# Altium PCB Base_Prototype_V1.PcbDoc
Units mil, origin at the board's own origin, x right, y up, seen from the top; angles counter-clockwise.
Board outline 4328.9 x 1639.92 mil, 2 copper layers (Top Layer, Bottom Layer); 71 components, 85 nets, 339 pads, 159 vias.
Unrouted connection lines stored in the file: 97.
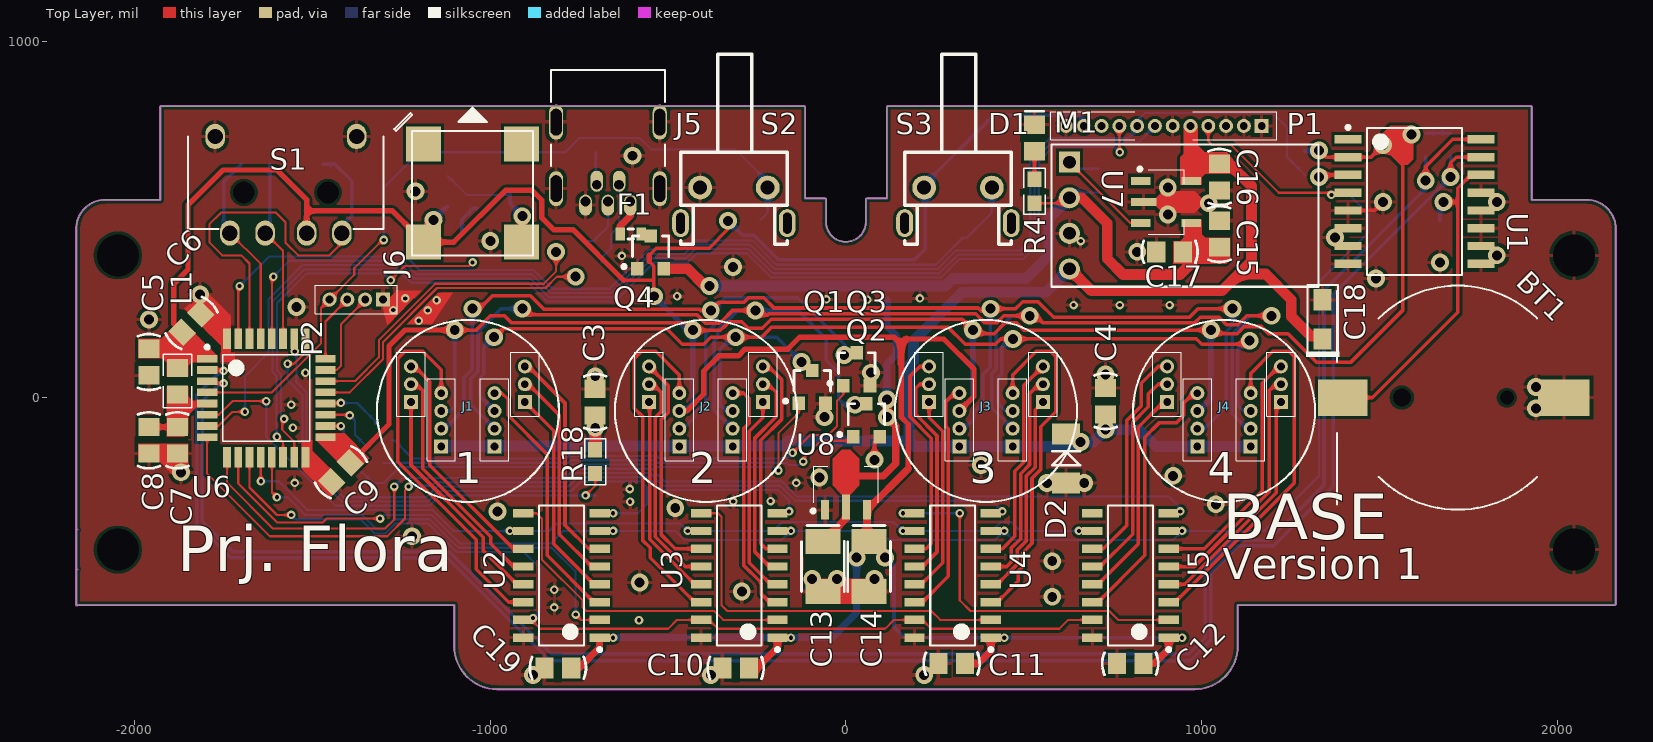
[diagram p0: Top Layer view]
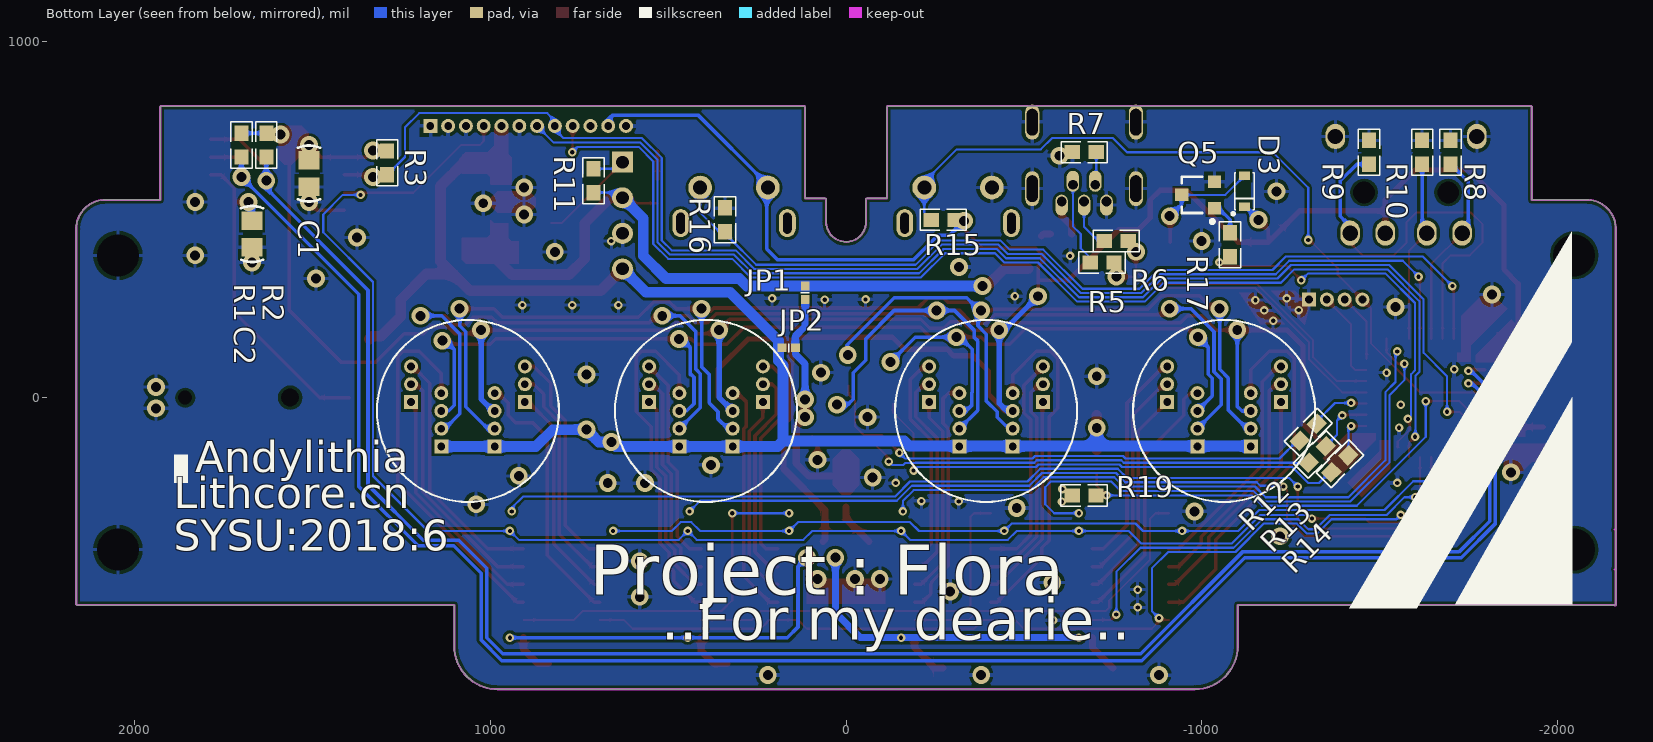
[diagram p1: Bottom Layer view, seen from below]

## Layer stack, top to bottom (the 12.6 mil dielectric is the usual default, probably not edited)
Top Solder: solder mask 0.4, Solder Resist, Dk 3.5
Top Layer: signal copper 1.4
Dielectric 1: dielectric 12.6, FR-4, Dk 4.8
Bottom Layer: signal copper 1.4
Bottom Solder: solder mask 0.4, Solder Resist, Dk 3.5

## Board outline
-2161.42,-583.68 -1101.39,-583.68 -1101.39,-698.82 ccw(c-980.32,-698.82) -981.2,-819.89 ccw(c-980.31,-816.93) -980.31,-820.02 ccw(c-980.31,-816.93) -979.44,-819.9 980.31,-819.9 ccw(c980.31,-698.82) 1101.39,-698.82 1101.39,-583.68 2161.42,-583.68 ccw(c2161.42,-580.71) 2164.39,-580.71 2164.39,473.54 ccw(c2161.42,474.41) 2164.51,474.41 ccw(c2161.42,474.41) 2164.38,475.3 ccw(c2082.68,474.41) 2082.68,556.12 1928.16,556.12 1928.16,816.93 ccw(c1925.2,816.93) 1925.2,819.9 118.11,819.9 ccw(c118.11,816.93) 115.14,816.93 115.14,560.05 59.06,560.05 ccw(c59.06,557.09) 56.09,557.09 56.05,496.06 ccw(c59.02,496.06) 56.06,495.96 cw(c0,494.09) 56.09,494.09 cw(c0,494.09) -56.06,495.96 ccw(c-59.02,496.06) -56.05,496.06 ccw(c-59.02,496.06) -56.05,496.06 -56.09,557.09 cw(c-59.06,557.09) -56.09,557.09 ccw(c-59.06,557.09) -59.06,560.05 -115.14,560.05 -115.14,816.93 ccw(c-118.11,816.93) -118.11,819.9 -1925.2,819.9 ccw(c-1925.2,816.93) -1928.16,816.93 -1928.16,556.12 -2082.68,556.12 ccw(c-2082.68,474.41) -2164.39,474.41 ccw(c-2161.42,474.41) -2164.39,474.39 -2164.39,-580.71 ccw(c-2161.42,-580.71)

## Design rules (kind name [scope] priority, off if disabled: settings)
AssemblyTestPointUsage [All] p1 off:
AssemblyTestpoint [All] p1 off: testpointundercomponent=TRUE minsize=40 maxsize=100 preferedsize=60 minholesize=0 maxholesize=40 preferedholesize=32 testpointgrid=1 usegrid=TRUE gridtolerance=0.01 allowsidetop=TRUE allowsidebottom=TRUE
Clearance [All] p1: gap=6 ignorepadtopadclearanceinfootprint=FALSE except(0: Arc-Hole Track-Hole SMDPad-Hole THPad-Hole Via-Hole Fill-Hole Poly-Hole Region-Hole Text-Hole; 8: Arc-Fill Arc-Poly Arc-Region Track-Fill Track-Poly Track-Region SMDPad-Fill SMDPad-Poly SMDPad-Region THPad-Fill THPad-Poly THPad-Region Via-Fill Via-Poly Via-Region Fill-Fill Fill-Poly Fill-Region Poly-Poly Poly-Region Region-Region)
ComponentClearance [All] p1 off: gap=10 collisioncheckmode=3 verticalgap=10 showdistances=FALSE
FabricationTestPointUsage [All] p1 off: valid=0 allowmultiple=FALSE
FabricationTestpoint [All] p1 off: side=3 testpointundercomponent=TRUE minsize=40 maxsize=100 preferedsize=60 minholesize=0 maxholesize=40 preferedholesize=32 testpointgrid=1 allowsidetop=TRUE allowsidebottom=TRUE usegrid=TRUE gridtolerance=0.01
FanoutControl Fanout_BGA [IsBGA] p1 off: bgadir=Out bgaviamode=Centered fanoutstyle=Auto fanoutdirection=Alternating viagrid=1 // Fanout_BGA (Default Rule)
FanoutControl Fanout_LCC [IsLCC] p2 off: bgadir=Out bgaviamode=Centered fanoutstyle=Auto fanoutdirection=Alternating viagrid=1 // Fanout_LCC (Default Rule)
Height [All] p1 off: minheight=0 maxheight=1000 prefheight=500
MinimumSolderMaskSliver [All] p1 off: minsoldermaskwidth=10
PolygonConnect [All] p1: connectstyle=Relief reliefconductorwidth=10 reliefentries=4 polygonreliefangle="90 Angle" airgapwidth=10
RoomDefinition RTCModule [InComponentClass('RTCModule')] p1: confinementstyle=ConfineIn formatcopy=TRUE lockcomponents=FALSE outline 1245,-330 2105,-330 2105,790 1245,790
RoomDefinition IV9Driv [InComponentClass('IV9Driv')] p2: confinementstyle=ConfineIn formatcopy=TRUE lockcomponents=FALSE outline -1335,-805 1335,-805 1335,270 -1335,270
RoomDefinition TOP [InComponentClass('TOP')] p3: confinementstyle=ConfineIn formatcopy=TRUE lockcomponents=FALSE outline -2005,-595 1480,-595 1480,1050 -2005,1050
RoutingVias [All] p1: holewidth=28 width=50 viastyle="Through Hole" minholewidth=28 minwidth=50 maxholewidth=28 maxwidth=50
SilkToSilkClearance [All] p1 off: silktosilkclearance=10
SilkToSolderMaskClearance [IsPad] p1 off: minsilkscreentomaskgap=10 clearancetoexposedcopper=TRUE
SolderMaskExpansion [All] p1: expansion=4
Width [All] p1: maxlimit=50 minlimit=6 preferedwidth=10 minimp=50.000000 maximp=50.000000 favimp=50.000000
19 further rules are at their usual default settings.

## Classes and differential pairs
component class RTCModule: BT1 C1 C2 R1 R2 R3 U1
component class TOP: C3 C4 C5 C6 C7 C8 C9 C13 C14 C15 C16 C17 C18 D1 D3 F1 J5 J6 JP1 JP2 L1 M1 P1 P2 Q4 Q5 R4 R5 R6 R7 R8 R9 R10 R11 R12 R13 R14 R15 R16 R17 R18 R19 S1 S2 S3 U6 U7 U8
component class IV9Driv: C10 C11 C12 C19 D2 J1 J2 J3 J4 Q1 Q2 Q3 Q? U2 U3 U4 U5

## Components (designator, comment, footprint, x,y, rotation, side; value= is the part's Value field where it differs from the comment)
BT1 "CR1220" CR1220_Holder_SMT 1720.47,0 r180 top
C1 "Cap" C-RAD-0805 1510,630 r90 bottom value=100nF
C2 "Cap" C-RAD-0805 1670,460 r90 bottom value=100nF
C3 "Cap" C-RAD-0805 -705,-12.6 r270 top value=10uF
C4 "Cap" C-RAD-0805 730,-10 r270 top value=10uF
C5 "Cap" C-RAD-0805 -1960,100 r90 top value=1uF
C6 "Cap" C-RAD-0805 -1840,210 r225 top value=100nF
C7 "Cap" C-RAD-0805 -1880,-120 r90 top value=1uF
C8 "Cap" C-RAD-0805 -1960,-120 r90 top value=100nF
C9 "Cap" C-RAD-0805 -1420,-210 r45 top value=100nF
C10 "Cap" C-RAD-0805 -310,-760 r0 top value=100nF
C11 "Cap" C-RAD-0805 297.24,-748.03 r0 top value=100nF
C12 "Cap" C-RAD-0805 799.21,-748.03 r0 top value=100nF
C13 "Cap Pol" CAP-3528 -65,-475 r270 top value=10uF
C14 "Cap Pol" CAP-3528 65,-475 r270 top value=10uF
C15 "Cap" C-RAD-0805 1050,460 r270 top value=100n
C16 "Cap" C-RAD-0805 1050,620 r90 top value=100n
C17 "Cap" C-RAD-0805 910,410 r0 top value=1u
C18 "Cap Pol" CAP-3216 1340,220 r90 top value=10uF
C19 "Cap" C-RAD-0805 -810,-760 r0 top value=100nF
D1 "USB_PPresent" LED_0805 530,730 r90 top
D2 "Diode-Z" DIODE-1206 618.7,-240 r90 top value=5.1V
D3 "Diode" "SOD323 - INV" -1120,580 r90 bottom
F1 "Fuse" J1-0603 -605,460 r0 top value=800mA
J1 "Kartusche" KARTUSCHE_HDR_EConn -1062.99,-37.4 r0 top
J2 "Kartusche" KARTUSCHE_HDR_EConn -393.7,-37.4 r0 top
J3 "Kartusche" KARTUSCHE_HDR_EConn 393.7,-37.4 r0 top
J4 "Kartusche" KARTUSCHE_HDR_EConn 1062.99,-37.4 r0 top
J5 "USB-Mini-TypeB" USB_MINI_TypeB -669.29,551.18 r90 top locked
J6 "Buzzer" 8530S_BUZZER -1050,575 r270 top
JP1 "JMP" R0402 115,295 r270 bottom
JP2 "JMP" R0402 161.3,140 r180 bottom
L1 "Inductor" 0805-1 -1880,46.26 r90 top value=Bead
M1 "MP2315_Module" MP2315_Module 728.35,511.81 r0 top
P1 "Header 12" HDR12X1_1.27mm 893.7,763.78 r180 top
P2 "Header 4" HDR4X1_1.27mm -1301.95,275.76 r180 top
Q1 "MOSFET-N-E" SOT-23 -95,30 r0 top
Q2 "MOSFET-N-E" SOT-23 57.4,-63.74 r0 top
Q3 "MOSFET-N-E" SOT-23 30,80 r0 top
Q4 "MOSFET-P-E" SOT-23 -549.28,408.3 r0 top
Q5 "MOSFET-N-E" SOT-23 -990,570 r90 bottom
R1 "Res1" 0603-1 1700,710 r90 bottom value=10K
R2 "Res1" 0603-1 1630,710 r90 bottom value=10K
R3 "Res1" 0603-1 1290,660 r90 bottom value=10K
R4 "Res1" 0603-1 530,580 r90 top value=10K
R5 "Res1" 0603-1 -720,380 r0 bottom value=100K
R6 "Res1" 0603-1 -760,440 r0 bottom value=100K
R7 "Res1" 0603-1 -670,690 r180 bottom value=100K
R8 "Res1" 0603-1 -1700,690 r90 bottom value=10K
R9 "Res1" 0603-1 -1470,690 r90 bottom value=10K
R10 "Res1" 0603-1 -1620,690 r90 bottom value=10K
R11 "Res1" 0603-1 710,610 r90 bottom value=10K
R12 "Res1" 0603-1 -1300,-97.32 r315 bottom value=20
R13 "Res1" 0603-1 -1325,-160 r315 bottom value=20
R14 "Res1" 0603-1 -1388.66,-186.34 r315 bottom value=20
R15 "Res1" 0603-1 -273.46,500 r0 bottom value=10K
R16 "Res1" 0603-1 340,500 r90 bottom value=10K
R17 "Res1" 0603-1 -1080,430 r90 bottom value=20
R18 "Res1" 0603-1 -705,-180 r270 top value=10K
R19 "Res1" 0603-1 -669.29,-275 r0 bottom value=10K
S1 "Quad Encoder" SIQ-02FVS1_03_r -1574.8,753.94 r0 top locked
S2 "SW-PB" SW_PB2_C1 -314.96,590.55 r0 top locked
S3 "SW-PB" SW_PB2_C1 314.96,590.55 r0 top locked
U1 "DS3231" "16 SO (Maxim W16#H2)" 1598.43,551.18 r0 top
U2 "TLC6C598" SOIC16N -800,-500 r180 top
U3 "TLC6C598" SOIC16N -300,-500 r180 top
U4 "TLC6C598" SOIC16N 300,-500 r180 top
U5 "TLC6C598" SOIC16N 800,-500 r180 top
U6 "STM32 MCU" TQFP80P900X900X160-32N -1297.24,-333.66 r0 top
U7 "XC6503CZxx-G" SOT-89-5 900,550 r0 top
U8 "HT73XX LDO" SOT89-150P409X160-3N 0,-245 r90 top

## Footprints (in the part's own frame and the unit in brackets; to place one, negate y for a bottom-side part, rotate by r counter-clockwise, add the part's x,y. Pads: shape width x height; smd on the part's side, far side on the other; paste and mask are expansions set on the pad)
"16 SO (Maxim W16#H2)" [mm] "SOP, 16-Leads, Body 10.30x7.50mm, Pitch 1.27mm, IPC Medium Density"
  rect 1.9x0.6 smd: 1(-4.75,4.445) 2(-4.75,3.175) 3(-4.75,1.905) 4(-4.75,0.635) 5(-4.75,-0.635) 6(-4.75,-1.905) 7(-4.75,-3.175) 8(-4.75,-4.445) 9(4.75,-4.445) 10(4.75,-3.175) 11(4.75,-1.905) 12(4.75,-0.635) 13(4.75,0.635) 14(4.75,1.905) 15(4.75,3.175) 16(4.75,4.445)
  silkscreen extent -4.87,-5.25 3.4,5.42, body extent -5.16,-5.25 5.16,5.25, height 2.65
0603-1 [mm] "贴片带丝印"
  rect 1.1x1 smd: 1(-0.85,0) 2(0.85,0)
  silkscreen extent -1.65,-0.76 1.65,0.76, body extent -1.14,-0.38 1.14,0.38, height 1
0805-1 [mm] "贴片带丝印"
  rect 1.3x1.5 smd: 1(-0.95,0) 2(0.95,0)
  silkscreen extent -1.91,-1.02 1.91,1.02, body extent -1.14,-0.51 1.14,0.51, height 1
8530S_BUZZER [mm] "8530S SMT MAGNETIC BUZZER TRANSDUCER"
  rect 2.5x2.5 smd: 1(-3.5,-3.5) 2(3.5,-3.5) 3(3.5,3.5) 4(-3.5,3.5)
  silkscreen extent -6.1,-5.59 4.44,4.32, body extent -4.45,-4.35 4.45,4.35, height 3
C-RAD-0805 [mm] "贴片电容"
  rect 1.3x1.5 smd: 1(-0.95,0) 2(0.95,0)
  silkscreen extent -2,-0.79 2,0.79, body extent -1.27,-0.64 1.27,0.64, height 0.9
CAP-3216 [mil] "钽电容"
  rect 60x50 smd: 1(-55,0) 2(55,0)
  silkscreen extent -106,-48 96,46
CAP-3528 [mm] "钽电容"
  rect 1.8x2.5 smd: 1(-1.778,0) 2(1.778,0)
  silkscreen extent -2.92,-1.52 1.78,1.52, body extent -1.91,-1.4 1.91,1.4, height 1.1
CR1220_Holder_SMT [mm]
  round 0 hole 1 unplated: 0(-3.5,0)
  rect 3.54x2.6 smd: 1(8.23,0)
  rect 3.66x2.6 smd: 2(-7.57,0)
  round 0 hole 1.3 unplated: 9(4,0)
  silkscreen extent -5.66,-8 8.64,8, body extent -9.27,-7.5 9.27,7.5, height 4
DIODE-1206 [mm] "玻璃封装二极管"
  rect 1.5x2 smd: 1(0,0) 2(3.5,0)
  silkscreen extent 1.25,-1 2.25,1
HDR4X1_1.27mm [mm]
  rect 1x1 hole 0.55: 1(0,0)
  round 1 hole 0.55: 2(1.27,0) 3(2.54,0) 4(3.81,0)
  silkscreen extent -1.02,-1.02 4.83,1.02
HDR12X1_1.27mm [mm]
  rect 1x1 hole 0.55: 1(-6.985,0)
  round 1 hole 0.55: 2(-5.715,0) 3(-4.445,0) 4(-3.175,0) 5(-1.905,0) 6(-0.635,0) 7(0.635,0) 8(1.905,0) 9(3.175,0) 10(4.445,0) 11(5.715,0) 12(6.985,0)
  silkscreen extent -8.08,-1 8.08,1
J1-0603 [mm] "Chip Resistor, Body 1.6x0.8mm, IPC High Density"
  rect 0.7x0.9 smd: 1(-0.75,0) 2(0.75,0)
  silkscreen extent -0.2,-0.35 0.2,0.35, body extent -0.85,-0.48 0.85,0.48, height 0.9
KARTUSCHE_HDR_EConn [mm] "IV9 Module"
  rect 1x1 hole 0.55: 1(1.905,-2.54) 5(4.064,0.635) 10(-4.064,0.635) 14(-1.905,-2.54)
  round 1 hole 0.55: 2(1.905,-1.27) 3(1.905,0) 4(1.905,1.27) 6(4.064,1.905) 7(4.064,3.175) 8(-4.064,3.175) 9(-4.064,1.905) 11(-1.905,1.27) 12(-1.905,0) 13(-1.905,-1.27)
  silkscreen extent -6.5,-6.5 6.5,6.5, body extent -5.11,-3.37 5.11,4.01, height 4.3
LED_0805 [mm] "贴片二极管"
  rect 1.3x1.5 smd: 1(-0.95,0) 2(0.95,0)
  silkscreen extent 1.91,-0.63 1.91,0.64
MP2315_Module [mm]
  rect 1.5x1.5 hole 0.9: 1(-2.54,3.81)
  round 1.5 hole 0.9: 2(-2.54,1.27) 3(-2.54,-1.27) 4(-2.54,-3.81)
  silkscreen extent -3.81,-5.08 15.24,5.08
R0402 [mm] "Chip Resistor, 2-Leads, Body 1,0x0,5mm, IPC High Density"
  rect 0.65x0.6 smd mask+0: 1(-0.475,0) 2(0.475,0)
  silkscreen extent 0,-0.3 0,0.3, body extent -0.5,-0.25 0.5,0.25, height 0.38
SIQ-02FVS1_03_r [mm] "Mitsumi Quadrature Encoder Thru Hole Mount"
  round 0 hole 1.55 unplated: 0(-3,-4.5) 0(3,-4.5)
  oval 1.4x1.8 hole 1.1: 1(-4,-7.4) 2(-1.48,-7.4) 3(1.48,-7.4) 4(4,-7.4) 5(-5.05,-0.5) 5(5.05,-0.5)
  silkscreen extent -6.98,-7.11 6.98,-0.51, body extent -7,-7.12 7,7.13, height 5
"SOD323 - INV" [mm] "Molded SOD323, Body 2,7X1,35(MAX)"
  rect 0.6x0.8 smd mask+0: 1(1.1,0) 2(-1.1,0)
  silkscreen extent -1.7,-0.7 1.33,0.9, body extent -1.4,-0.67 1.4,0.68, height 1.1
SOIC16N [mm] "SOIC, 16-Leads, Body 9.90x3.90mm, Pitch 1.27mm, IPC Medium Density"
  rect 1.45x0.6 smd: 1(-2.725,4.445) 2(-2.725,3.175) 3(-2.725,1.905) 4(-2.725,0.635) 5(-2.725,-0.635) 6(-2.725,-1.905) 7(-2.725,-3.175) 8(-2.725,-4.445) 9(2.725,-4.445) 10(2.725,-3.175) 11(2.725,-1.905) 12(2.725,-0.635) 13(2.725,0.635) 14(2.725,1.905) 15(2.725,3.175) 16(2.725,4.445)
  silkscreen extent -2.85,-5 1.6,5.42, body extent -3,-5 3,5, height 1.75
SOT89-150P409X160-3N [mm] "SOT89, 3-Leads, Body 4.50x2.44mm, Pitch 1.50mm, Lead Span 4.1mm, IPC Medium Density"
  rect 1.4x0.6 smd: 1(-1.8,1.499) 3(-1.8,-1.499)
  rect 1.8x0.6 smd: 2(-1.6,0)
  Top Layer region: -0.7,0.3 -0.05,0.95 1.85,0.95 2.5,0.3 2.5,-0.3 1.85,-0.95 -0.05,-0.95 -0.7,-0.3
  silkscreen extent -2,-2.3 1.32,2.47, body extent -2.19,-2.3 1.8,2.3, height 1.6
SOT-23 [mm]
  rect 0.9x0.95 smd: 1(-0.95,-1.175) 2(0.95,-1.175) 3(0,1.175)
  silkscreen extent -2.03,-1.14 1.3,1.18
SOT-89-5 [mm]
  rect 1.4x0.6 smd: 1(-1.8,1.499) 3(-1.8,-1.499) 4(1.8,-1.499) 5(1.8,1.499)
  rect 1.8x0.6 smd: 2(-1.6,0)
  Top Layer region: -0.7,0.3 -0.238,0.762 2.038,0.762 2.5,0.3 2.5,-0.3 2.038,-0.762 -0.238,-0.762 -0.7,-0.3
  silkscreen extent -2,-2.3 1.32,2.47, body extent -1.27,-2.29 1.27,2.29, height 1.5
SW_PB2_C1 [mm] "侧卧微动开关"
  round 1.7 hole 1: 1(-2.413,0) 2(2.413,0)
  oval 1.2x2 hole 0.6 slot 1.5 at 90 deg: 3(-3.81,-2.54) 4(3.81,-2.54)
  silkscreen extent -3.81,-4.06 3.81,9.53
TQFP80P900X900X160-32N [mm] "TQFP, 32-Leads, Body 7.00x7.00mm, Pitch 0.80mm, IPC Medium Density"
  rect 1.45x0.55 smd: 1(-12.675,11.25) 2(-12.675,10.45) 3(-12.675,9.65) 4(-12.675,8.85) 5(-12.675,8.05) 6(-12.675,7.25) 7(-12.675,6.45) 8(-12.675,5.65) 17(-4.225,5.65) 18(-4.225,6.45) 19(-4.225,7.25) 20(-4.225,8.05) 21(-4.225,8.85) 22(-4.225,9.65) 23(-4.225,10.45) 24(-4.225,11.25)
  rect 0.55x1.45 smd: 9(-11.25,4.225) 10(-10.45,4.225) 11(-9.65,4.225) 12(-8.85,4.225) 13(-8.05,4.225) 14(-7.25,4.225) 15(-6.45,4.225) 16(-5.65,4.225) 25(-5.65,12.675) 26(-6.45,12.675) 27(-7.25,12.675) 28(-8.05,12.675) 29(-8.85,12.675) 30(-9.65,12.675) 31(-10.45,12.675) 32(-11.25,12.675)
  silkscreen extent -12.8,5.35 -5.35,12.2, body extent -12.95,3.95 -3.95,12.95, height 1.6
USB_MINI_TypeB [mm]
  oval 1.5x0.9 hole 0.7 copper offset -0.25,0: 1(0,-1.6) 3(0,0) 5(0,1.6)
  oval 1.5x0.9 hole 0.7 copper offset 0.25,0: 2(1.2,-0.8) 4(1.2,0.8)
  rrect100% 2.5x1 hole 0.8 slot 1.9 at 0 deg: 6(0.92,3.7) 6(0.92,-3.7) 6(5.67,-3.7) 6(5.67,3.7)
  silkscreen extent 2.54,-4.06 9.4,4.06, body extent -0.35,-3.85 9.5,3.85, height 5.8

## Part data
BT1: library part Battery_1, "备份电池"
C1 C2 C3 C4 C5 C6 C7 C8 C9 C10 C11 C12 C15 C16 C17 C19: "无极性电容"
C13 C14 C18: "极性电解电容"
D1: library part LED0, "发光二极管"
D2: "稳压二极管"
D3: "二极管", PackageDocument=Sep-1996
F1: library part "Fuse 2", "保险丝"
J1 J2 J3 J4: library part Kartusche_EConn, "IV9 Module"
J5: library part USB-Mini_TypeB
J6: library part Buzzer_8530S_SMT, "Surface Mount Buzzer"
JP1 JP2: "Generic Jumper"
L1: "电感"
M1: "MP2315 3A Step-down Module"
P1 P2: "接插件"
Q1 Q2 Q3 Q5: "N-Channel Enhanced MOSFET", PackageDocument=1995/1996
Q4: "P-Channel Enhanced MOSFET", PackageDocument=1995/1996
R1 R2 R3 R4 R5 R6 R7 R8 R9 R10 R11 R12 R13 R14 R15 R16 R17 R18 R19: "贴片电阻"
S1: library part SIQ_02FVS1, "Slide and Rotary Encoder Switches"
S2 S3: "微动开关"
U1: "Extremely Accurate I2C-Integrated RTC/TCXO/Crystal"
U2 U3 U4 U5: library part TLC6C598-Q1, "Power Logic 8-Bit Shift Register LED Driver"
U6: library part STM32F042K6T6, "ARM?-based 32-bit MCU, up to 32 KB Flash, crystal-less USB FS 2.0, CAN, 9 timers, ADC and comm. interfaces, 2.0 - 3.6 V"
U7: library part XC6503, "TOREX CL Capacitor-Less 500mA Low Power Consumption High Speed LDO Regulator"
U8: library part HT73xx, "HOLTEK Low Power Consumption LDO"

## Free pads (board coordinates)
  round 0 hole 118.11 unplated: 2(-2047.24,-427.17) 2(-2047.24,399.61) 2(2047.24,-427.17) 2(2047.24,399.61) 2(2047.24,399.61)

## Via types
v1: diameter 50, hole 28, Top Layer to Bottom Layer, 84 vias
v2: diameter 24, hole 11.81, Top Layer to Bottom Layer, 75 vias

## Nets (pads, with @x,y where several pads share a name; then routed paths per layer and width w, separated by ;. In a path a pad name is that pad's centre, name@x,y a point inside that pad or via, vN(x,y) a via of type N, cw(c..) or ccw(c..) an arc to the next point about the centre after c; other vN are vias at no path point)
3V3: C1.2 C5.2 C6.2 C9.2 C10.2 C11.2 C12.2 C14.1 C19.2 D3.2 J1.12 J2.12 J3.12 J4.12 J6.2 L1.2 P1.11 R1.2 R2.2 R3.2 R15.1 S1.3 S3.1 U1.2 U2.1 U3.1 U4.1 U5.1 U6.1 U6.17 U8.3 | length 13879.4
  Top Layer w10: C6.2 -1796.26,113.37 U6.1 ; U6.17 -1463.58,-113.52 C9.2@-1403.55,-173.55 ; J6.2 -1187.8,472.2 v1(-1160,500) ; v1(-1100,190) -1040,190 -1000,230 -960,230 -940,210 -450.71,210 v1(-430.71,190) -429.71,189 -353.34,189 -343.84,198.5 -343.12,198.5 -328.62,213 -293,213 -275,195 -235,195 -210,220 326.69,220 v1(356.69,190) 366.69,180 416.69,180 446.69,210 480,210 500,190 v1(1025.98,190) 1035.98,180 1100,180 1120,200 1167.36,200 1187.36,180 1242.63,180 1322.63,100 1420,100 1565,245 1565,655 v1(1510,710) 1476.18,676.18 U1.2 1348.68,676.18 v1(1330,694.86) ; -625,330 -540.6,330 ; -553.32,383.32 -540.6,370.6 -540.6,330 ; -553.32,400.53 -533.53,420.32 -384.82,420.32 -332,473.14 v1(-332,497) ; v1(-540,285) -540.6,285.6 -540.6,330
  Top Layer w15: C5.2 C5.2@-1933.74,137.4 ; L1.2 C5.2@-1933.74,137.4 ; S1.3 -1516.54,525 ; C9.2 -1285,-75 -1285,145 -1240,190 v1(-1100,190) ; -625,330 -767.2,472.2 -822.2,472.2 -855,505 -855,555 -882.6,582.6 -957.4,582.6 -1102.8,437.2 J6.2 -1275.59,525 -1516.54,525 ; -553.32,383.32 -553.32,400.53 ; J2.12 -447.4,-37.4 -400,10 -400,75 -357.5,117.5 -302.5,117.5 -283.75,136.25 -163.75,136.25 -130,170 135,170 155,150 ; 155,95 155,-55 175,-75 175,-199.87 ; 170,165 275,165 360,80 360,3.9 J3.12 ; C5.2@-1933.74,137.4 -1912.6,137.4 C6.2 -1890,207.11 -1890,320 -1850,360 -1850,541.81 -1751.81,640 -1600,640 -1516.54,556.54 -1516.54,525
  Top Layer w20: C19.2@-750,-760 -692.72,-702.72 U2.1 ; C10.2 -250,-760 -192.72,-702.72 U3.1 ; C14.1 59,-399 U8.3 175,-199.87 ; 155,95 155,150 170,165 ; C11.2 371.97,-748.03 407.28,-712.72 U4.1 ; C12.2 866.97,-748.03 907.28,-707.72 U5.1
  Bottom Layer w10: v1(-1160,500) -1123.31,536.69 D3.2 ; J1.12 -1112.4,-37.4 -1100,-25 v1(-1100,190) ; v1(-332,497) -292,457 -259.17,457 -189.87,387.7 192.7,387.7 223.07,418.07 223.07,601.54 416,794.46 655.54,794.46 668.7,781.3 P1.11 ; v1(110,-450) 135,-475 135,-645 165,-675 v2(445,-675) v2(945,-675) ; R3.2 1328.6,693.46 v1(1330,694.86) ; R2.2 R1.2
  Bottom Layer w15: v1(-540,285) -445,190 v1(-430.71,190) -430.71,-15.71 -452.4,-37.4 J2.12 ; J3.12 356.69,0.59 v1(356.69,190) ; J4.12 992.6,-37.4 1025.98,-4.02 v1(1025.98,190)
  Bottom Layer w20: v2(-655,-675) v2(-155,-675) -40,-675 30,-605 v1(30,-450)
  other v1: 1590,740
ADC_IN0: R18.2 R19.1 U6.6 | length 1374.5
  Top Layer w6: U6.6 -1763.23,-48.23 -1725,-10 v2(-1630,-10) ; v2(-732.28,-275) -705,-247.72 R18.2
  Bottom Layer w6: v2(-1630,-10) -1630,-110 -1436,-304 -1170.06,-304 -1141.06,-275 v2(-732.28,-275) R19.1
AUX_KEY: R16.1 S3.2 U6.31 | length 2552.6
  Top Layer w6: U6.31 -1708.66,310.04 v2(-1705,313.7)
  Bottom Layer w6: v2(-1705,313.7) -1622.02,396.68 -1236.68,396.68 -1199,359 -878.09,359 -825.09,306 -664.91,306 -554.91,416 -459.91,416 -433.91,442 -263.97,442 -195.67,373.7 252.79,373.7 329.09,450 340,450 409.96,519.96 S3.2
GND: BT1.2 C1.1 C2.1 C3.1 C4.1 C5.1 C6.1 C7.1 C8.1 C9.1 C10.1 C11.1 C12.1 C13.2 C14.2 C15.1 C16.1 C17.1 C18.2 C19.1 D1.2 D2.1 J5.5 J5.6 M1.3 P1.1 P1.2 P1.3 P1.6 P1.12 P2.1 pad.2@2047.24,399.61 pad.2@2047.24,-427.17 Q1.2 Q2.2 Q3.2 Q4.1 Q5.2 R7.1 R8.2 R9.2 R10.2 R16.2 R19.2 S1.5 S2.1 U1.5 U1.6 U1.7 U1.8 U1.9 U1.10 U1.11 U1.12 U1.13 U2.16 U3.16 U4.16 U5.16 U6.16 U6.32 U7.2 U8.1 | length 370.2
  Top Layer w10: C6.1 -1811.25,236.45 U6.32 ; U6.16 -1515.57,-167.32 C9.1@-1456.45,-226.45 ; v1(80,-175) 80,-124.8 Q2.2 ; U1.5 1486.18,526.18 v1(1510,550)
  other v1: -880,-780 -380,-780 220,-780 580,-560 -293,-545 -580,-520 -95,-510 -25,-510 80,-510 580,-460 -1220,-390 -980,-320 -480,-310 1040,-300 565,-240 670,-240 -75,-225 920,-220 -1870,-210 380,-190 -60,-55 1940,-30 1940,30 -705,60 730,65 70,70 -1960,220 -1545,255 -1816.34,289.56 1490,335 -318,367 1670,380 1830,400 818.7,410 -1000,440 1375,450 905,515 1020,546.54 1830,550 -1210,580 905,590.55 -600,680
  other v2: -582,-626 -820,-590 -820,-540 -607,-293 -317,-292 -212,-291 -608,-257 -1550,-240 -140,-240 -1555,-85 -1560,-20 -1520,70 -1710,80 -1201,216 -1176,245 -1273,246 640,260 770,260 910,260 -1151,274 60,275 -55,276 -1239,279 208,279 -475,285 -630,398.56 660,440
GPIO_EXTI5: P1.8 R3.1 U1.3 U6.28 | length 3753.9
  Top Layer w6: U6.28 -1614.17,335.83 v2(-1610,340)
  Top Layer w10: v1(1330,620) 1336.18,626.18 U1.3
  Bottom Layer w6: v2(-1610,340) -1565.32,384.68 -1246.02,384.68 -1208.34,347 -883.06,347 -830.06,294 -659.94,294 -549.94,404 -454.94,404 -428.94,430 -268.94,430 -200.64,361.7 257.76,361.7 310.06,414 490.06,414 518,441.94 518,674 574,730 795,730 818.7,753.7 P1.8 818.7,778.7 840,800 1200,800 1240,760 1240,676.54 R3.1
I2C1_SCL: R2.1 U1.16 U6.3 | length 5353.7
  Top Layer w10: U6.3 -1790,40 v2(-1750,40) ; v1(1630,610) 1630,650 1706.18,726.18 U1.16
  Bottom Layer w10: v2(-1750,40) -1760,40 -1810,-10 -1810,-347.37 -1723.37,-434 -1114.74,-434 -828.74,-720 965,-720 1010,-675 1010,-479.8 1088.8,-401 1188.6,-401 1344,-245.6 1344,302.23 1630,588.23 v1(1630,610) R2.1
I2C1_SDA: R1.1 U1.15 U6.2 | length 5377.2
  Top Layer w10: U6.2 -1752.24,77.76 -1750,75.51 v2(-1750,75) ; v1(1700,620) 1700,660 1716.18,676.18 U1.15
  Bottom Layer w10: v2(-1750,75) -1757.53,75 -1826,6.53 -1826,-354 -1730,-450 -1121.37,-450 -831.37,-740 967.63,-740 1026,-681.63 1026,-494 1103,-417 1203,-417 1370,-250 1370,290.91 1699.09,620 v1(1700,620) R1.1
IV9_LATCH: U2.10 U3.10 U4.10 U5.10 U6.12 | length 2479.8
  Top Layer w6: U6.12 -1645.67,-229.33 v2@-1645,-230
  Bottom Layer w6: v2(-1645,-235) -1595,-235 -1514,-316 -1162.03,-316 -1103.03,-375 v2(-945,-375) -835,-375 -814,-354 -466,-354 v2(-445,-375) -205,-375 -180,-350 135,-350 v2(160,-375) 410,-375 435,-350 465,-350 490,-375 v2(655,-375)
NetBT1_1: BT1.1 C2.2 U1.14 | length 949.6
  Top Layer w10: BT1.1 1480,0 1720,240 1720,550 ; v1(1680,550) 1720,550 ; U1.14 1757.09,626.18 1720,589.09 1720,550
  Bottom Layer w10: C2.2 1670,540 v1(1680,550)
NetC7_2: C7.2 C8.2 L1.1 U6.5 | length 265.8
  Top Layer w15: C8.2 C7.2 L1.1 -1875.59,8.86 -1850,-16.73 U6.5
NetC13_1: C13.1 JP1.2 JP2.2 U8.2 | length 767.9
  Top Layer w20: C13.1 0,-340 U8.2 ; 5,-220 105,-220 140,-185 140,-80 v1(115,-55) v1(115,-5)
  Bottom Layer w20: v1(115,-5) 115,95 142.6,122.6 JP2.2 142.6,172.4 115,200 JP1.2
NetD1_1: D1.1 R4.2 | length 79.1
  Top Layer w10: R4.2 D1.1
NetD3_1: D3.1 J6.3 Q5.3 | length 346
  Top Layer w10: J6.3 -912.2,507.8 v1(-910,510)
  Bottom Layer w6: D3.1 -1066.69,570 Q5.3
  Bottom Layer w10: Q5.3 -943.74,543.74 v1(-910,510)
NetF1_1: F1.1 J5.1 | length 102.9
  Top Layer w20: F1.1 -634.53,482.96 -606.3,511.19 J5.1
NetF1_2: F1.2 Q4.3 | length 28.4
  Top Layer w20: F1.2 -554.72,460 Q4.3
NetJ1_2: J1.2 J2.2 J3.2 J4.2 Q2.3 | length 4437.5
  Top Layer w10: v1(-910,250) -910,246 -923,233 -418.91,233 -394.91,209 -355.96,209 -350.46,214.5 -349.75,214.5 -319.25,245 v1(-255,245) -242,232 -220.63,232 -216.63,236 365,236 391,210 424.07,210 444.07,230 v1(516.69,230) 535,230 555,210 980,210 996,226 1049.07,226 1070.07,205 1101.69,205 1126.69,230 v1(1196.69,230)
  Bottom Layer w10: J1.2 -1055,-20.39 -1055,52.37 -1034.68,72.7 -1034.68,185.32 -970,250 v1(-910,250) ; J2.2 -370,-36.1 -370,7.37 -371,8.37 -371,159 -360,170 -360,190 -305,245 v1(-255,245) -135,245 -55,165 -55,105 -20,70 -20,-5 5,-30 15,-20 v1(25,-20) ; J3.2 410,-28.7 410,67.37 422.02,79.39 422.02,185.32 466.69,230 v1(516.69,230) ; J4.2 1127.4,-87.4 1085.69,-45.69 1085.69,179 1136.69,230 v1(1196.69,230)
NetJ1_3: J1.3 J2.3 J3.3 J4.3 Q1.3 | length 3429.6
  Top Layer w10: v1(-990,170) -988.28,168.28 -962.56,194 -504,194 -460,150 -400,150 -380,170 v1(-310,170) -237.37,170 -209.37,198 287,198 335,150 420,150 435,165 v1(470,165) 474.94,165 475,165.06 984.94,165.06 1000,150 1115,150 1125,160 v1(1135,160)
  Bottom Layer w10: v1(-990,170) -1018.68,141.32 -1018.68,66.07 -1030,54.75 -1030,4.61 J1.3 ; J2.3 -337.6,-37.4 -354,-21 -354,14 -355,15 -355,135.71 -320.71,170 v1(-310,170) -195,170 v1(-125,100) ; J3.3 447.4,-37.4 427.5,-17.5 427.5,57.5 435,65 438.02,65 438.02,141.32 461.69,165 v1(470,165) ; v1@1135.98,170 1101.69,135.71 1101.69,-21.69 1117.4,-37.4 J4.3
NetJ1_4: J1.4 U2.3 | length 731.1
  Top Layer w10: J1.4 -967.6,12.6 -950,-5 -950,-50 -840,-160 -840,-443.43 -708.43,-575 U2.3
NetJ1_5: J1.5 U2.4 | length 608.9
  Top Layer w10: J1.5 -822,-93.39 -822,-411.43 -708.43,-525 U2.4
NetJ1_6: J1.6 U2.5 | length 618.8
  Top Layer w10: J1.6 -892.6,37.6 -806,-49 -806,-384 -715,-475 U2.5
NetJ1_7: J1.7 U2.6 | length 623.8
  Top Layer w10: J1.7 -892.6,87.6 -790,-15 -790,-358.43 -723.43,-425 U2.6
NetJ1_8: J1.8 U2.11 | length 665.7
  Top Layer w10: J1.8 -1212.6,87.6 -1170,45 -1170,-190 -935,-425 U2.11
NetJ1_9: J1.9 U2.12 | length 668.6
  Top Layer w10: J1.9 -1207.6,37.6 -1190,20 -1190,-200 -998.75,-391.25 -998.75,-411.25 -935,-475 U2.12
NetJ1_10: J1.10 U2.13 | length 653.7
  Top Layer w10: J1.10 -1222.99,-189.64 -1020,-392.63 -1020,-430 -925,-525 U2.13
NetJ1_11: J1.11 U2.14 | length 1072.1
  Top Layer w10: J1.11 -1137.99,77.99 -1190,130 -1240,130 -1260,110 -1260,-180 -1040,-400 -1040,-482.88 -947.88,-575 U2.14
NetJ1_13: J1.13 J2.13 J3.13 J4.13 Q3.3 | length 4278.1
  Top Layer w10: v1(-1050,250) -1030,250 -994,286 -887.26,286 -850.26,249 -412.28,249 -408.28,245 v1(-380,245) -357.5,267.5 -287.58,267.5 -274.08,281 -231.49,281 -202.49,252 371.63,252 380.63,243 399.69,243 v1(406.69,250) 476.69,250 496.69,270 540,270 584,226 966,226 990,250 v1(1086.69,250)
  Bottom Layer w10: J1.13 -1127.4,-87.4 -1075,-35 -1075,55 -1050.68,79.32 -1050.68,249.32 v1(-1050,250) ; J2.13 -468.7,-79 -449,-79 -425,-55 -425,-40 -394.71,-9.71 -394.71,177.92 -371,201.63 -371,241 v1@-375,245 ; v1(-5,120) -5,145 -2.5,147.5 -136,281 -339,281 v1@-375,245 ; J3.13 332.6,-87.4 360,-60 360,-40 385,-15 385,65 406.02,86.02 406.02,249.32 v1(406.69,250) ; J4.13 1007.6,-87.4 1069.69,-25.31 1069.69,185.63 1085.69,201.63 1085.69,241 1076.69,250 v1(1086.69,250) ; v1@-375,245 -380,250 v1(-380,245) v1@-375,245
NetJ2_4: J2.4 U3.3 | length 683.8
  Top Layer w10: J2.4 -287.6,12.6 -272.6,-2.4 -272.6,-72.57 -288,-87.97 -288,-471.05 -241.21,-517.84 -241.21,-520.74 -239.32,-522.63 -239.32,-522.84 -238,-524.16 -238,-552 -215,-575 U3.3
NetJ2_5: J2.5 U3.4 | length 572.3
  Top Layer w10: J2.5 -233.7,-56.3 -272,-94.6 -272,-464.43 -211.43,-525 U3.4
NetJ2_6: J2.6 U3.5 | length 601.2
  Top Layer w10: J2.6 -218.6,37.6 -196,15 -196,-53.37 -256,-113.37 -256,-434 -215,-475 U3.5
NetJ2_7: J2.7 U3.6 | length 607.6
  Top Layer w10: J2.7 -217.6,87.6 -180,50 -180,-60 -240,-120 -240,-410 -225,-425 U3.6
NetJ2_8: J2.8 U3.11 | length 632.3
  Top Layer w10: J2.8 -500,33.9 -500,-42.63 -520,-62.63 -520,-384.75 -479.75,-425 U3.11
NetJ2_9: J2.9 U3.12 | length 617.8
  Top Layer w10: J2.9@-537.7,31.63 -543.67,37.6 -542.6,37.6 -520,15 -520,-40 -536,-56 -536,-391.37 -452.37,-475 U3.12
NetJ2_10: J2.10 U3.13 | length 583.6
  Top Layer w10: J2.10 -552,-14.1 -552,-398 -425,-525 U3.13
NetJ2_11: J2.11 U3.14 | length 980.4
  Top Layer w10: J2.11@-468.7,18.5 -468.7,63.7 -535,130 -575,130 -595,110 -595,-30 -571.9,-53.1 -571.9,-400.73 -550,-422.63 -550,-450 -425,-575 U3.14
NetJ3_4: J3.4 U4.3 | length 982.1
  Top Layer w10: U4.3 425,-575 485,-515 485,-487.63 496.96,-475.67 496.96,-435.92 523,-409.88 523,-227 548,-202 548,-82 590,-40 590,115 575,130 535,130 468.7,63.7 J3.4
NetJ3_5: J3.5 U4.4 | length 583.6
  Top Layer w10: U4.4 425,-525 480.96,-469.04 480.96,-429.29 507,-403.25 507,-220.37 532,-195.37 532,-34.1 J3.5
NetJ3_6: J3.6 U4.5 | length 606.2
  Top Layer w10: U4.5 452.37,-475 464.96,-462.41 464.96,-422.67 491,-396.63 491,-213.75 516,-188.75 516,11 542.6,37.6 J3.6
NetJ3_7: J3.7 U4.6 | length 592.4
  Top Layer w10: U4.6 440,-425 475,-390 475,-207.12 500,-182.12 500,33.9 J3.7
NetJ3_8: J3.8 U4.11 | length 613.5
  Top Layer w10: U4.11 225,-425 240,-410 240,-113.84 180,-53.84 180,60 207.6,87.6 J3.8
NetJ3_9: J3.9 U4.12 | length 607.6
  Top Layer w10: U4.12 215,-475 256,-434 256,-107.21 196,-47.21 196,26 207.6,37.6 J3.9
NetJ3_10: J3.10 U4.13 | length 571
  Top Layer w10: U4.13 211.43,-525 272,-464.43 272,-94.6 233.7,-56.3 J3.10@233.7,-13.7
NetJ3_11: J3.11 U4.14 | length 655.6
  Top Layer w10: U4.14 215,-575 288,-502 288,-87.97 280,-79.97 280,-12.54 J3.11@306.37,13.83
NetJ4_4: J4.4 U5.3 | length 1055.8
  Top Layer w10: U5.3 925,-575 1260,-240 1260,115 1245,130 1200,130 1137.99,67.99 J4.4
NetJ4_5: J4.5 U5.4 | length 669.8
  Top Layer w10: U5.4 952.37,-525 1210,-267.37 1210,-25.39 J4.5
NetJ4_6: J4.6 U5.5 | length 694.8
  Top Layer w10: U5.5 979.75,-475 1190,-264.75 1190,20 1207.6,37.6 J4.6
NetJ4_7: J4.7 U5.6 | length 705
  Top Layer w10: U5.6 1007.12,-425 1170,-262.12 1170,40 1217.6,87.6 J4.7
NetJ4_8: J4.8 U5.11 | length 632.6
  Top Layer w10: U5.11 723.43,-425 790,-358.43 790,-63.37 830,-23.37 830,40 877.6,87.6 J4.8
NetJ4_9: J4.9 U5.12 | length 627.6
  Top Layer w10: U5.12 715,-475 806,-384 806,-70 850,-26 850,10 877.6,37.6 J4.9
NetJ4_10: J4.10 U5.13 | length 615
  Top Layer w10: U5.13 708.43,-525 822,-411.43 822,-83 892.6,-12.4 J4.10
NetJ4_11: J4.11 U5.14 | length 753.7
  Top Layer w10: U5.14 708.43,-575 840,-443.43 840,-111.26 880,-71.26 928.74,-71.26 950,-50 950,-15 977.6,12.6 J4.11
NetJ5_2: J5.2 R5.2 | length 238.6
  Bottom Layer w6: R5.2 -686.54,393.46 -660,420 -660,460 -637.8,482.2 J5.2
NetJ5_3: J5.3 R6.2 | length 144.6
  Bottom Layer w6: R6.2 -710,440 -669.29,480.71 J5.3
NetJ5_4: J5.4 R7.2 | length 92.7
  Bottom Layer w6: R7.2 -703.46,601.1 J5.4
NetM1_1: M1.1 R11.2 U7.3 | length 360.8
  Top Layer w6: M1.1 799.16,491 U7.3
  Bottom Layer w6: M1.1 646.69,643.46 R11.2
NetQ1_1: Q1.1 R14.2 | length 1428.6
  Top Layer w6: v2(-190,-205) -190,-100 -132.4,-42.4 Q1.1
  Bottom Layer w6: R14.2 -1360,-210 -1330,-240 -1300,-240 -1255,-195 -775.91,-195 -768.91,-188 -541.09,-188 -534.09,-195 -200,-195 v2(-190,-205)
NetQ2_1: Q2.1 R13.2 | length 1362.2
  Top Layer w6: v2(-120,-180) -120,-170 -71.26,-121.26 Q2.1@17.6,-121.26
  Bottom Layer w6: R13.2 -1260.63,-183.66 -1259.97,-183 -780.88,-183 -773.88,-176 -536.12,-176 -529.12,-183 -195.03,-183 -194.37,-183.66 -166.34,-183.66 -160,-190 -130,-190 v2(-120,-180)
NetQ3_1: Q3.1 R12.2 | length 1437.1
  Top Layer w6: v2(-150,-155) -100,-105 -50,-105 -25,-80 -25,-8.86 -7.4,8.74 Q3.1
  Bottom Layer w6: R12.2 -1269.01,-120.99 -1219,-171 -785.85,-171 -778.85,-164 -531.15,-164 -524.15,-171 -190.06,-171 -189.4,-171.66 -166.66,-171.66 v2(-150,-155)
NetQ5_1: Q5.1 R17.2 | length 93.8
  Bottom Layer w10: R17.2 -1080,500 -1047.4,532.6 Q5.1
NetU2_9: U2.9 U3.2 | length 917.9
  Top Layer w6: U2.9 -870,-325 -855,-340 -855,-455 -740,-570 -740,-590 -730,-600 -370,-600 -345,-625 U3.2
NetU3_9: U3.9 U4.2 | length 1084.7
  Top Layer w6: U3.9 -360,-325 -350,-335 -350,-584 -334,-600 240,-600 265,-625 U4.2
NetU4_9: U4.9 U5.2 | length 1015.1
  Top Layer w6: v2(320,-325) 320,-570 350,-600 740,-600 765,-625 U5.2
  Bottom Layer w6: v2(160,-325) v2(320,-325)
NetU5_9: U5.9
NRST: P2.4 R15.2 S2.2 U6.4 | length 2192.9
  Top Layer w6: U6.4 -1613.65,14.76 -1475.58,152.83 -1475.58,252.13 P2.4 -1382.71,345 -1382.71,363.79 v2@-1301.5,445
  Bottom Layer w6: v2(-1299.62,443.14) -1299.62,590.38 -1200,690 -790,690 -750,730 -580,730 -548,698 -311.41,698 -219.96,606.56 S2.2 -219.96,520.04 R15.2
OUT_EN: P1.9 U6.14 | length 3360.5
  Top Layer w6: v2(-1600,-110) -1582.68,-127.32 U6.14 ; P1.9 768.7,691.3 v2(770,690)
  Bottom Layer w6: v2(-1600,-110) -1601,-109 -1601,61 -1612,72 -1612,271.03 -1522.34,360.68 -1260.68,360.68 -1223,323 -893,323 -840,270 -650,270 -540,380 -445,380 -419,406 -278.88,406 -210.58,337.7 267.7,337.7 320,390 500,390 542.03,432.03 542.03,451.91 ; 542,451.94 542,664.06 582.94,705 755,705 v2(770,690)
PERIPH_NRST: P1.4 U1.4 U2.7 U3.7 U4.7 U5.7 U6.10 | length 4757
  Top Layer w6: U6.10 -1708.66,-241.34 -1599,-351 -1471,-351 -1460,-340 v2(-1310,-340) ; P1.4 1018.7,721.3 1030,710 1083.09,710 1216.91,576.18 U1.4
  Bottom Layer w6: v2(-1310,-340) -1300,-330 -1165,-330 -1085,-410 -830,-410 -795,-375 v2(-655,-375) -480,-375 -455,-400 -180,-400 v2(-155,-375) 95,-375 120,-400 420,-400 v2(445,-375) 470,-400 920,-400 v2(945,-375) 1175.2,-375 1330,-220.2 1330,325 1470,465 1470,515 1415,570 v2(1365,570)
QUAD_A: R8.1 S1.1 U6.29 | length 555.1
  Top Layer w6: S1.1 -1645.67,375.98 U6.29
  Bottom Layer w10: S1.1 -1732.28,472.28 -1750,490 -1750,606.54 R8.1
QUAD_B: R9.1 S1.4 U6.30 | length 1169.9
  Top Layer w6: U6.30 -1677.17,377.17 -1700,400 -1753.62,400 -1790,436.38 -1790,487.4 -1757.4,520 -1602.6,520 -1575.79,493.19 -1575.79,435.79 -1540,400 -1452.2,400 -1417.32,434.88 S1.4
  Bottom Layer w10: R9.1 -1436.54,656.54 -1390,610 -1390,510 -1417.32,482.68 S1.4
QUAD_KEY: R10.1 S1.2 U6.27 | length 517.5
  Top Layer w6: S1.2 -1582.68,412.2 U6.27
  Bottom Layer w10: S1.2 -1620,475.67 R10.1
SPI1_MOSI: U2.2 U6.13 | length 1262.2
  Top Layer w6: U6.13 -1614.17,-265.83 v2(-1600,-280) ; v2(-760,-610) -745,-625 U2.2
  Bottom Layer w6: v2(-1600,-280) -1570,-280 -1520,-330 -1360,-330 -1320,-370 -1300,-370 -1272,-342 -1169.97,-342 -1089.97,-422 -828,-422 -760,-490 v2(-760,-610)
SPI1_SCK: U2.15 U3.15 U4.15 U5.15 U6.11 | length 2830.4
  Top Layer w6: U6.11 -1677.17,-252.83 -1600,-330 v2(-1560,-330) ; U2.15 -885,-625 -860,-650 -500,-650 -475,-625 U3.15 -385,-625 -360,-650 110,-650 135,-625 U4.15 215,-625 240,-650 600,-650 625,-625 U5.15
  Bottom Layer w6: v2(-1560,-330) -1548,-342 -1364.97,-342 -1324.97,-382 -1295.03,-382 -1267.03,-354 -1174.94,-354 -1094.94,-434 -906,-434 -860,-480 -860,-600 v2(-880,-620)
SWIRE: P1.7 U6.7 | length 3428.5
  Top Layer w6: U6.7 -1764.72,-79.72 -1725,-40 v2(-1690,-40)
  Bottom Layer w6: v2(-1690,-40) -1690,60 -1624,126 -1624,276 -1527.32,372.68 -1250.99,372.68 -1213.31,335 -888.03,335 -835.03,282 -654.97,282 -544.97,392 -449.97,392 -423.97,418 -273.91,418 -205.61,349.7 262.73,349.7 315.03,402 495.03,402 530.03,437 530.03,446.94 ; 530,446.97 530,669.03 577.97,717 821.92,717 P1.7
SYS_SWCLK: P2.3 U6.24 | length 192
  Top Layer w6: U6.24 -1463.58,214.13 P2.3
SYS_SWDIO: P2.2 U6.23 | length 262.6
  Top Layer w6: U6.23 -1432.24,77.76 -1420,90 -1420,206.42 -1351.95,274.46 P2.2
TIM1_CH1: R14.1 U6.18 | length 129.5
  Top Layer w6: U6.18 -1420.28,-79.72 v2(-1420,-80)
  Bottom Layer w6: v2(-1420,-80) -1412.33,-87.67 R14.1
TIM1_CH2: R13.1 U6.19 | length 174.8
  Top Layer w6: U6.19 -1396.77,-48.23 v2(-1395,-50)
  Bottom Layer w6: v2(-1395,-50) -1380,-65 -1380,-105 R13.1
TIM1_CH3: R12.1 U6.20 | length 169.2
  Top Layer w6: U6.20 -1421.73,-16.73 v2(-1420,-15)
  Bottom Layer w6: v2(-1420,-15) -1375,-15 -1323.66,-66.34 R12.1
TIM2_CH1: U2.8 U6.25 | length 1592.9
  Top Layer w6: v2(-1570,95) -1551.97,95 -1519.69,127.29 U6.25
  Bottom Layer w6: v2(-1570,95) -1570,49 -1528.54,7.54 -1528.54,-181.46 -1418,-292 -1175.03,-292 -1146.03,-263 -773,-263 -746,-236 -576,-236 -560,-252 -560,-300 -585,-325 v2(-655,-325)
TIM2_CH2: U3.8 U6.26 | length 1800.3
  Bottom Layer w6: v2(-1550,130) -1545,125 -1545,44 -1516.54,15.54 -1516.54,-176.49 -1413.03,-280 -1180,-280 -1150,-250 -780,-250 -754,-224 -556,-224 -520,-260 -190,-260 -160,-290 v2(-160,-320)
TIM2_CH3: U4.8 U6.8 | length 2577.1
  Top Layer w6: U6.8 -1796.26,-213.74 -1620,-390 -1290,-390 -1240,-340 -1240,-260 v2(-1230,-250)
  Bottom Layer w6: v2(-1230,-250) -1228,-248 -1164.97,-248 -1154.97,-238 -784.97,-238 -758.97,-212 -551.03,-212 -515.03,-248 -185.03,-248 -143.03,-290 410,-290 v2(440,-320)
TIM2_CH4: U5.8 U6.9 | length 2985.4
  Top Layer w6: U6.9 -1740.16,-239.84 -1612,-368 -1295,-368 -1270,-343 v2(-1270,-250)
  Bottom Layer w6: v2(-1270,-250) -1246,-226 -789.94,-226 -763.94,-200 -546.06,-200 -510.06,-236 -180.06,-236 -138.06,-278 908,-278 940,-310 v2(940,-320)
TIM14_CH1: R17.1 U6.15 | length 1043.1
  Top Layer w6: v2(-1580,-60) -1585,-65 -1585,-90 -1551.18,-123.82 U6.15@-1551.18,-140 ; v2(-1280,330) -1240,370 -1060,370 v2(-1050,380)
  Bottom Layer w6: v2(-1580,-60) -1589,-51 -1589,65.97 -1600,76.97 -1600,266.06 -1517.37,348.68 -1298.68,348.68 v2(-1280,330)
USB_DN: R5.1 U6.21 | length 866.3
  Top Layer w6: U6.21 -1395.24,14.76 -1301.5,108.5 -1301.5,156.24 -1149.74,308 -844.83,308 -812.83,340 v1(-760,340)
USB_DP: R6.1 U6.22 | length 859.6
  Top Layer w6: U6.22 -1380.71,46.26 -1313.5,113.47 -1313.5,161.22 -1154.72,320 -849.81,320 -814.96,354.84 v1(-814.96,410)
V_ANODE: C3.2 C4.2 C16.2 C18.1 D2.2 J1.1 J1.14 J2.1 J2.14 J3.1 J3.14 J4.1 J4.14 JP2.1 M1.4 P1.5 R18.1 U7.5 | length 4523.3
  Top Layer w30: R18.1 v1(-705,-85) C3.2 ; M1.4 690.16,300 1056.89,300 1104.29,347.4 ; C16.2 1077.6,657.4 1140,595 1140,383.11 1104.29,347.4 ; C18.1 1332.5,172.5 1307.5,172.5 1252,228 1252,275.4 1180,347.4 1104.29,347.4
  Bottom Layer w30: J1.14 -1136.59,-136 -705,-136 ; v1(-705,-85) -705,-136 ; M1.4 562.54,296 326,296 190,160 190,103.42 177,90.42 177,-122 ; J4.1 J4.14 872.4,-137.4 825,-90 v1(730,-90) 695,-125 v1(660,-125) 647.6,-137.4 J3.1 J3.14 192.4,-137.4 177,-122 ; -705,-136 -177.67,-136 -163.67,-122 177,-122
V_RAW: C15.2 C17.2 JP1.1 M1.2 Q4.2 R4.1 R11.1 U7.4 | length 2039.4
  Top Layer w6: R4.1 613.07,546.54 M1.2
  Top Layer w30: Q4.2 -444.56,362.04 -396.22,313.7 v1(-383.7,313.7) ; M1.2 663.19,561.81 735,490 735,390 779,346 938.99,346 984.35,391.36
  Bottom Layer w6: M1.2 643.07,576.54 R11.1
  Bottom Layer w30: v1(-383.7,313.7) JP1.1 278.7,313.7 300,335 506,335 570,399 570,503.46 M1.2
pads on no net: BT1.0 BT1.9 J6.1 J6.4 P1.10 S1.0 S2.3 S2.4 S3.3 S3.4 U1.1 U7.1

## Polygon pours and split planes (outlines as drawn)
GND on Top Layer "GND_L01_P000" (solid, remove dead copper, pour order 0): -2255,870 -2225,900 2255,900 2255,-790 2055,-990 2005,-940 -2310,-940
GND on Bottom Layer "GND_L02_P002" (solid, remove dead copper, pour order 2): -2295,1085 2030,1085 2290,825 2290,-835 2135,-835 1895,-1075 -2464.76,-1075

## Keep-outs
Keep-Out Layer:
  lines w5.91: -2164.39,-583.8 -2164.39,473.54 cw(c-2161.42,474.41) -2164.51,474.41 cw(c-2161.42,474.41) -2164.38,475.3 cw(c-2082.68,474.41) -2082.68,556.12 -1928.16,556.12 -1928.16,816.06 cw(c-1925.2,816.93) -1928.29,816.93 cw(c-1925.2,816.93) -1925.2,820.02 ; -2164.39,-579.84 ccw(c-2161.42,-580.71) -2164.51,-580.71 ccw(c-2161.42,-580.71) -2161.42,-583.8 ccw(c-2161.42,-580.71) -2160.55,-583.68 -1101.39,-583.68 -1101.39,-698.82 ccw(c-980.32,-698.82) -981.2,-819.89 ccw(c-980.31,-816.93) -980.31,-820.02 ccw(c-980.31,-816.93) -979.44,-819.9 980.31,-819.9 ccw(c980.31,-698.82) 1101.39,-698.82 1101.39,-583.68 2161.42,-583.68 ccw(c2161.42,-580.71) 2164.39,-580.71 2164.39,473.54 ccw(c2161.42,474.41) 2164.51,474.41 ccw(c2161.42,474.41) 2164.38,475.3 ccw(c2082.68,474.41) 2082.68,556.12 1928.16,556.12 1928.16,816.93 ccw(c1925.2,816.93) 1925.2,819.9 118.11,819.9 ccw(c118.11,816.93) 115.14,816.93 115.14,560.05 59.06,560.05 ccw(c59.06,557.09) 56.09,557.09 56.05,496.06 ccw(c59.02,496.06) 56.06,495.96 cw(c0,494.09) 56.09,494.09 cw(c0,494.09) -56.06,495.96 ccw(c-59.02,496.06) -56.05,496.06 ; -2164.39,-486.22 cw(c-2161.42,-486.22) -2161.42,-483.25 ; -2164.39,-368.11 ccw(c-2161.42,-368.11) -2161.42,-371.08 ; -1925.2,820.02 cw(c-1925.2,816.93) -1924.33,819.9 -118.11,819.9 cw(c-118.11,816.93) -115.14,816.93 -115.14,560.05 -59.06,560.05 cw(c-59.06,557.09) -56.09,557.09 ; -1925.2,820.02 -1925.2,820.02 ; -56.09,557.09 ccw(c-59.06,557.09) -56.09,557.09 ; -56.09,557.09 -56.05,496.06 ; -56.09,557.09 -56.09,557.09 ; -56.05,496.06 ccw(c-59.02,496.06) -56.05,496.06

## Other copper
Top Layer:
  pour cut-out: -820,-720 -800,-720 -800,-800 -820,-800
  region net GND: -1146,295 -1234.44,206.56 -1164.44,206.56 -1106,295
  region net GND: -1290,204 -1193.56,300.44 -1263.56,300.44 -1303.21,260.79
  pour cut-out: 557.37,-154.25 676.21,-154.25 676.64,-153.83 660,-137.18 660,-70 600,-70 580,-50 578,-52 548,-52
  pour cut-out: 570,586.06 570,566.06 490,566.06 490,586.06
  pour cut-out: 770,0 770,-20 690,-20 690,0
  pour cut-out: 789.21,-708.03 809.21,-708.03 809.21,-788.03 789.21,-788.03
  pour cut-out: -118.11,-440 110,-440 110,-510 -118.11,-510
  pour cut-out: -665,-173.94 -665,-193.94 -745,-193.94 -745,-173.94
  pour cut-out: -665,-2.6 -665,-22.6 -745,-22.6 -745,-2.6
  pour cut-out: -2000,-130 -2000,-110 -1920,-110 -1920,-130
  pour cut-out: 570,740 570,720 490,720 490,740
  pour cut-out: -320,-720 -300,-720 -300,-800 -320,-800
  pour cut-out: -1759.72,126.81 -1788.62,126.81 -1889.84,228.03 -1869.84,248.03 -1859.84,248.03 -1759.72,147.91
  pour cut-out: -1500.13,-128.78 -1471.22,-128.78 -1370,-230 -1390,-250 -1400,-250 -1500.13,-149.87
  region net GND: -1990,-130 -1850,-130 -1850,-220 -1890,-220 -1915.47,-194.53 -1915.47,-192.99 -1917.01,-192.99 -1930,-180 -1990,-180
  region net NetC7_2: -1910,30 -1850,30 -1850,3.97 -1836.03,-10 -1770,-10 -1770,-20 -1772.56,-27.44 -1827.44,-27.44 -1850,-50 -1850,-100 -1860,-110 -1910,-110
  region net GND: -1756.57,174.63 -1756.57,101.31 -1754.72,99.45 -1753.45,100.72 -1718.58,100.72 -1718.58,126.06 -1719.33,126.81 -1735.16,126.81 -1735.16,144.84 -1730,150
  region net GND: -1860,250 -1736.81,126.81 -1730,126.81 -1730,230 -1789.56,289.56 -1816.34,289.56
  region net 3V3: -1490,-100 -1410,-100 -1340,-170 -1390,-220 -1490,-120
  region net GND: -1530,-120 -1530,-200 -1450,-280 -1410,-240 -1500.13,-149.87 -1500.13,-120
  region net GND: -110,-510 110,-510 110,-580 -110,-580
  region net 3V3: 1565,655 1510,710 1510,745 1530,765 1595,765 1595,750 1610,735 1595,720 1595,670 1580,655
  region net 3V3: -1990,165.35 -1924.65,165.35 -1870,220 -1834.42,184.42 -1830,184.42 -1830,180 -1770,120 -1770,100 -1840,100 -1850,90 -1850,60 -1910,60 -1910,97.4 -1922.6,110 -1990,110
  region net V_ANODE: 950,763.78 950,670 1018.7,670 1018.7,679.72 988.43,710 988.43,763.35 987.99,763.78
  region net V_ANODE: 940,598.43 998.43,598.43 1000,600 1000,620 1010,630 1080,630 1080,680 1070,690 953.82,690 940,676.18
  region net V_RAW: 920,440 940,440 950,450 950,490 988.43,490 998.43,500 1000,498.43 1000,460 1010,450 1080,450 1080,387.48 1068.7,376.18 920,376.18
Bottom Layer:
  pour cut-out: 311.72,513.28 311.72,485 368.28,485 368.28,513.28
  pour cut-out: -657.5,721.82 -685.79,721.82 -685.79,665.25 -657.5,665.25
  pour cut-out: -1140,613.5 -1140,560.05 -1095.25,560.05 -1095.25,613.5
  pour cut-out: -285.96,468.18 -257.68,468.18 -257.68,524.75 -285.96,524.75
  pour cut-out: -1731.82,702.5 -1731.82,674.21 -1675.25,674.21 -1675.25,702.5
  pour cut-out: -1651.82,702.5 -1651.82,674.21 -1595.25,674.21 -1595.25,702.5
  pour cut-out: -1506.82,707.5 -1506.82,679.21 -1450.25,679.21 -1450.25,707.5
  pour cut-out: -1111.82,442.5 -1111.82,414.21 -1055.25,414.21 -1055.25,442.5
  pour cut-out: -707.5,411.82 -735.79,411.82 -735.79,355.25 -707.5,355.25
  pour cut-out: -750.97,471.82 -779.25,471.82 -779.25,415.25 -750.97,415.25
  pour cut-out: 741.82,600.97 741.82,629.25 685.25,629.25 685.25,600.97
  pour cut-out: 1323.93,642.36 1323.93,670.65 1267.36,670.65 1267.36,642.36
  pour cut-out: 1731.82,697.5 1731.82,725.79 1675.25,725.79 1675.25,697.5
  pour cut-out: 1661.82,697.5 1661.82,725.79 1605.25,725.79 1605.25,697.5
  pour cut-out: 1536.82,618.57 1536.82,646.85 1480.25,646.85 1480.25,618.57
  pour cut-out: 1696.82,448.57 1696.82,476.85 1640.25,476.85 1640.25,448.57
  pour cut-out: -681.79,-306.82 -653.5,-306.82 -653.5,-250.25 -681.79,-250.25
  pour cut-out: -1331.34,-110.99 -1311.34,-130.99 -1271.34,-90.99 -1291.34,-70.99
  pour cut-out: -1356.34,-173.66 -1336.34,-193.66 -1296.34,-153.66 -1316.34,-133.66
  pour cut-out: -1420,-200 -1400,-220 -1360,-180 -1380,-160

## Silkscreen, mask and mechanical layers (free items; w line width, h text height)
Top Overlay:
  text "1" at -1100,-270 h150
  text "2" at -440,-270 h150
  text "3" at 347.4,-270 h150
  text "4" at 1016.69,-270 h150
  text "BASE" at 1060,-440 h220
  text "Prj. Flora" at -1880,-530 h220
  text "Version 1" at 1060,-540 h150
Bottom Overlay:
  circle w5.91: c1062.99,-37.4 r255.91
  circle w5.91: c393.7,-37.4 r255.91
  circle w5.91: c-393.7,-37.4 r255.91
  circle w5.91: c-1062.99,-37.4 r255.91
  rectangle: 1850,-240 1890,-160
  region: -1712.39,-580.71 -2041.42,-580.71 -2041.42,0.42
  region: -2040.55,467.04 -2040.55,155.33 -1604.47,-592.38 -1414.9,-592.38
  text "Andylithia" at 1830,-240 h150
  text "Lithcore.cn" at 1890,-340 h150
  text "SYSU:2018:6" at 1890,-460 h150
  text "Project : Flora" at 720,-600 h240
  text "..For my dearie.." at 520,-720 h200
Top Solder:
  rectangle: -115.14,363 115.14,560.05
  region: -2165,556 -2164.88,556.12 -1928.16,556.12 -1928.16,379.84 -2039,269 -2039,-4 -2180,-4 -2183,-1
  region: -2162.52,-601.95 -1927.16,-602.07 -1927.16,-379.84 -2038,-269 -2038,4 -2179,4 -2182,1
  region: 2162.52,-601.95 1927.16,-602.07 1927.16,-379.84 2038,-269 2038,4 2179,4 2182,1
  region: 2165,556 2164.88,556.12 1928.16,556.12 1928.16,379.84 2039,269 2039,-4 2180,-4 2183,-1
Bottom Solder:
  region: 2162.52,-601.95 1927.16,-602.07 1927.16,-379.84 2038,-269 2038,4 2179,4 2182,1
  region: 2165,556 2164.88,556.12 1928.16,556.12 1928.16,379.84 2039,269 2039,-4 2180,-4 2183,-1
  region: -2162.52,-601.95 -1927.16,-602.07 -1927.16,-379.84 -2038,-269 -2038,4 -2179,4 -2182,1
  region: -2165,556 -2164.88,556.12 -1928.16,556.12 -1928.16,379.84 -2039,269 -2039,-4 -2180,-4 -2183,-1
Mechanical 1:
  circle w5.91: c-2161.42,-580.71 r0.12
  circle w5.91: c-2161.42,474.41 r0.12
  circle w5.91: c-980.31,-816.93 r0.12
  circle w5.91: c2161.42,474.41 r0.12
  circle w5.91: c-1925.2,816.93 r0.12
  circle w5.91: c-1925.2,816.93 r0.12
  lines w5.91: -2161.42,-580.71 -2161.42,474.41 cw(c-2082.68,474.41) -2082.68,553.15 -1925.2,553.15 -1925.2,816.93 -118.11,816.93 -118.11,557.09 -59.06,557.09 -59.02,496.06 ccw(c0,494.09) 59.02,496.06 59.06,557.09 118.11,557.09 118.11,816.93 1925.2,816.93 1925.2,553.15 2082.68,553.15 cw(c2082.68,474.41) 2161.42,474.41 2161.42,-580.71 1098.43,-580.71 1098.43,-698.82 cw(c980.31,-698.82) 980.31,-816.93 -980.32,-816.93 cw(c-980.32,-698.82) -1098.43,-698.82 -1098.43,-580.71 -2161.42,-580.71
Mechanical 13:
  circle w5.91: c-2047.24,399.61 r59.06
  circle w5.91: c2047.24,399.61 r59.06
  lines w5.91: -2295,0 2290.24,0 ; -2290.24,0 2295,0 ; 0,-1063.56 0,954.72

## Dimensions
1925.2,819.9 to 980.31,-819.9 on Bottom Overlay
-2161.33,474.32 to 2161.42,-580.71 on Bottom Overlay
